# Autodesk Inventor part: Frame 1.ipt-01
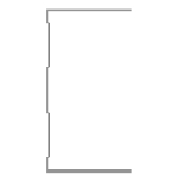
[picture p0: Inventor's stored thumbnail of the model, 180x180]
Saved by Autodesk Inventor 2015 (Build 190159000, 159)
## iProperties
_CCFamilyMember: 1
_CCFamilyDisplayName: Kévin - Kévin Novo
_FrameMemberDoc: Frame Member File
_Version: 15.0.0
_GetPNFromCC: 1
Created: 2015-04
Part Number: Frame 1.ipt-01
Material: Aluminum 6061
Description: Kévin Novo
Document SubType Name: Modeling
Standard: Kevin
Designer: suporte
Standards Organization: Kevin
Language: en-US
Size Designation: (Unnamed 1)
Categories: <MemberInstance><Categories><Category DisplayName="Structural Shapes" InternalName="089c4875-fa83-4c05-b084-43b9cc11f5ed" Mnemonic="GRDR"><CategoryParameter Dis
Density: 2.7 g/cm^3
Appearance: Aluminum - Flat
IsCustomPart: 1
G_L: 475,000 mm
G_W: 50,000 mm
G_H: 75,000 mm
+4E99D251-4782-4548-BCB7-0B26D6DB859E+CUTDETAIL1: Cut
+01FB47D4-333C-42F1-846E-D717AC291E9D+CUTDETAIL2: Cut
Author: suporte
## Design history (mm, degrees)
node "Start Plane"
node "End Plane"
sketch "Sketch"
  geometry: L1 (24.7, 37.5)-(24.7, 36.9); L2 (24.7, 36.9)-(-24.7, 36.9); L3 (-24.7, -36.9)-(24.7, -36.9); L4 (24.7, -36.9)-(24.7, -37.5); L5 (24.7, -37.5)-(-25.3, -37.5); L6 (-25.3, 37.5)-(24.7, 37.5); L7 (-24.7, 36.9)-(-24.7, 31.9); L8 (-24.7, 31.9)-(-23.3, 30.5); L9 (-23.3, 30.5)-(-23.3, 10.934); L10 (-23.3, 10.934)-(-24.7, 9.534); L11 (-24.7, 9.534)-(-24.7, -9.534); L12 (-24.7, -9.534)-(-23.3, -10.934); L13 (-23.3, -10.934)-(-23.3, -30.5); L14 (-23.3, -30.5)-(-24.7, -31.9); L15 (-24.7, -31.9)-(-24.7, -36.9); L16 (-25.3, -37.5)-(-25.3, -31.651); L17 (-25.3, -31.651)-(-23.9, -30.251); L18 (-23.9, -30.251)-(-23.9, -11.183); L19 (-23.9, -11.183)-(-25.3, -9.783); L20 (-25.3, -9.783)-(-25.3, 9.783); L21 (-25.3, 9.783)-(-23.9, 11.183); L22 (-23.9, 11.183)-(-23.9, 30.251); L23 (-23.9, 30.251)-(-25.3, 31.651); L24 (-25.3, 31.651)-(-25.3, 37.5); L25 (-25.3, 0)-(30.37, 0); 3 further points
  constraints: 50 end point, 10 point on line, 9 parallel, 5 perpendicular, 4 equal length, 3 midpoint, 3 vertical, 2 vertical alignment, 1 collinear, 1 horizontal, 1 horizontal alignment
  dimensions: "d3" = 0.6 distance of L1.start L1.end (= d6); "d5" = 75 distance between parallel lines of L5 L6; "d6" = 0.6 distance between parallel lines of L24 L7 (= d8); "d7" = 0.6 distance between parallel lines of L8 L23 (= d8); "d8" = 0.6 distance between parallel lines of L22 L9 (= d12); "Espessura" = 0.6 distance between parallel lines of L17 L14; "d10" = 0.6 distance between parallel lines of L13 L18 (= Espessura); "d11" = 0.6 distance between parallel lines of L12 L19 (= Espessura); "d12" = 0.6 distance between parallel lines of L21 L10 (= d11); "d13" = 5 distance of L2.end L7.end; "d15" = 135 deg angle of L9 L8; "d16" = 2 distance between parallel lines of L24 L9; "d17" = 50 distance of L6.start L1.start
extrude "Body" join sketch "Sketch" stored distance "d24" = 0.13; taper "d25" = 0 deg
node "Driven Length"
  sketch "Sketch10"
    geometry: L1 (0, 0)-(10, 0) reference
    constraints: 2 end point, 1 horizontal
  workplane "Work Plane7"
  sketch "Sketch11"
    geometry: L1 (-2, 12.5)-(12, 12.5) reference; L2 (-2, 487.5)-(12, 487.5) reference
    dimensions: "d27" = 475 distance between parallel lines of L1 L2 (derived)
workplane "Work Plane8"
split "Split1"
workplane "Work Plane9"
split "Split2"
body "Solid1"
other parameters: "G_OFFSET_START" = -12.5 [user parameter; used in 1 equation term], "G_OFFSET_END" = -12.5 [user parameter; used in 1 equation term], "d22" = 12.5 (= -G_OFFSET_START), "d23" = 487.5 (= tamanho + G_OFFSET_END), "G_L" = 475 (= d27) [user parameter], "d34" = 90 deg
